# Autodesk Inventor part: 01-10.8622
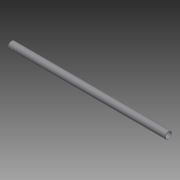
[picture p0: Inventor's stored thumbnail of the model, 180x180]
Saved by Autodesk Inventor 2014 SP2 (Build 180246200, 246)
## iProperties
Created: 2020-01
Part Number: 01-10.8622
Material: Generic
Catalog Web Link: www.cadenas.de
Description: Tube-Original Line - Standard Air Cylinders
Vendor: BIMBA
Document SubType Name: Modeling
Designer: psadmin
Manufacturer: BIMBA
Mass: 4.89669 g
Surface Area: 205.859 cm^2
Volume: 4.89669 cm^3
Density: 1 g/cm^3
Appearance: PSOLRGB-180-180-180
Category: PARTsolutions
Company: BIMBA
Title: 01-10.8622
Author: Cadenas PARTsolutions
Comments: Original Line - Standard Air Cylinders
PSOL_IDENT_0: {$CADENAS_DATA\23d-libs\bimba\bimba_brand\bimba_imperial\bimba_full_line\original_line_cylinders\sta
PSOL_IDENT_1: ndard_air_cylinders\tube.prj},197 {VTYP=3D},{NB=01-10.8622},{LINA=01-10.8622},{NN=Tube},{DATE=23.12.
PSOL_IDENT_2: 2019 10:36:49},{GEOMDATE=18.02.2011 00:00:00},{VERSION=},{LINEID=20},{WBVAR=MNT,ACTING,NR,L,FOURHOLE
PSOL_IDENT_3: S,SR},{WBNUMERIC=L,FOURHOLES}  {NB=01-10.8622},{LINA=01-10.8622},{KT=DUMMY},{PN=01-10.8622},{BORE=0.
PSOL_IDENT_4: 43750000},{BOREPN=01},{MNT=},{MNTALG='' , 'Front Nose' , 'BF' , 'Front Block' , 'BFT' , 'Front Trunn
PSOL_IDENT_5: ion'},{ACTING=},{ACTINGALG= '' , 'Single Acting' , 'R' , 'Reverse/Double Acting' },{NR=},{NRALG= ''
PSOL_IDENT_6: , 'Without Non-rotating Rod' , 'NR' , 'With Non-rotating Rod' },{L=10.8620},{OD=0.4840},{ODN=0.4840}
PSOL_IDENT_7: ,{ODP=0.7380},{ODB=0.0000},{ID=0.4465},{DV=0.00000000},{LV=0.00000000},{LV1=0.00000000},{G=0.0200},{
PSOL_IDENT_8: FOURHOLES=2},{AA=0.2500},{BB=0.0620},{SR=},{SRALG= 'C' , 'Carbon Steel Rod' , 'SR' , '303 Stainless
PSOL_IDENT_9: Steel Rod' , '' , '303 Stainless Steel Rod'}
NN: Tube
NT: Original Line - Standard Air Cylinders
NB: 01-10.8622
NBSYN: $PN.
LINA: 01-10.8622
BORE: 0
BOREPN: 01
MNT: Front Nose
MNTALG: '' , 'Front Nose' , 'BF' , 'Front Block' , 'BFT' , 'Front Trunnion'
ACTING: Single Acting
NR: Without Non-rotating Rod
L: 10.862
ODN: 0.484
ODP: 0.738
ODB: 0
ID: 0.4465
DV: 0
LV: 0
LV1: 0
G: 0.02
FOURHOLES: 2
AA: 0.25
BB: 0.062
SR: 303 Stainless Steel Rod
SUPPLIER: BIMBA
ARTICLENO: 01-10.8622
BOMINFO: 01-10.8622
CREATOR: CADENAS GmbH
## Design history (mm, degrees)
sketch "Sketch_1"
  geometry: L1 (275.895, 0)-(0, 0); L2 (-0.396, 5.305)-(-0.254, 5.163); L3 (-0.254, 5.163)-(0, 5.163); L4 (0, 5.163)-(0.508, 5.671); L5 (0.508, 5.671)-(275.387, 5.671); L6 (275.387, 5.671)-(275.895, 5.163); L7 (275.895, 5.163)-(276.149, 5.163); L8 (276.149, 5.163)-(276.291, 5.305); L9 (276.291, 5.485)-(275.778, 5.998); L10 (275.419, 6.147)-(0.476, 6.147); L11 (0.117, 5.998)-(-0.396, 5.485); A1 r 0.127 centre (-0.307, 5.395) between (-0.396, 5.485) and (-0.396, 5.305); A2 r 0.127 centre (276.201, 5.395) between (276.291, 5.305) and (276.291, 5.485); A3 r 0.508 centre (275.419, 5.639) between (275.778, 5.998) and (275.419, 6.147); A4 r 0.508 centre (0.476, 5.639) between (0.476, 6.147) and (0.117, 5.998)
  constraints: 22 end point, 8 point on circle, 4 centre point
revolve "Revolution1" sketch "Sketch_1" stored, may be unused: angle "d0" = 360 deg
sketch "Sketch_4"
  geometry: C1 r 0.787 at (5.842, 0); 1 further point
  constraints: 1 centre point
extrude "Extrusion1" cut sketch "Sketch_4" distance "d1" = 6.1468; taper "d2" = 0 deg
node "cp1_XY"
node "cp1_YZ"
node "cp1_ZX"
node "cp1_X"
node "cp1_Y"
node "cp1_Z"
node "cp1_Center"
node "cp2_XY"
node "cp2_YZ"
node "cp2_ZX"
node "cp2_X"
node "cp2_Y"
node "cp2_Z"
node "cp2_Center"
node "cp3_XY"
node "cp3_YZ"
node "cp3_ZX"
node "cp3_X"
node "cp3_Y"
node "cp3_Z"
node "cp3_Center"
node "cp4_XY"
node "cp4_YZ"
node "cp4_ZX"
node "cp4_X"
node "cp4_Y"
node "cp4_Z"
node "cp4_Center"
node "tube_front_XY"
node "tube_front_YZ"
node "tube_front_ZX"
node "tube_front_X"
node "tube_front_Y"
node "tube_front_Z"
node "tube_front_Center"
node "tube_rear_XY"
node "tube_rear_YZ"
node "tube_rear_ZX"
node "tube_rear_X"
node "tube_rear_Y"
node "tube_rear_Z"
node "tube_rear_Center"
body "Solid1"
